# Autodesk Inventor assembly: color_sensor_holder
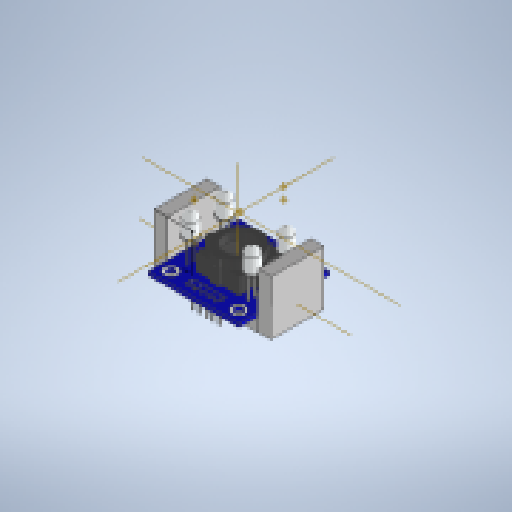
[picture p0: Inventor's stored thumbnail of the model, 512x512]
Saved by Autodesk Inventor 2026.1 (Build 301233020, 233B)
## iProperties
Created: 2026-10
Part Number: color_sensor_holder
Document SubType Name: Assembly
Designer: alolo
Author: alolo
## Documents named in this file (4)
- C:\Users\hp\Documents\Inventor\DOM1_CartesianRobot\color_sensor_holder.iam
- C:\Users\hp\Documents\Inventor\DOM1_CartesianRobot\color_sensor_holder_base.ipt
- C:\Users\hp\Documents\Inventor\DOM1_CartesianRobot\TCS3200 Color Sensor Module.ipt
- C:\Users\hp\Documents\Inventor\DOM1_CartesianRobot\color_sensor_holer_side.ipt
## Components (4 placed, 3 different names)
1. color_sensor_holder_base:1
2. TCS3200 Color Sensor Module:1 — Mate:1, Mate:13, Mate:33, Mate:34, Mate:35, Mate:36
3. color_sensor_holer_side:1 — Mate:31, Mate:39
4. color_sensor_holer_side:2 — Mate:15, Mate:40
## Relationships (10: Mate 10)
- Mate:1: TCS3200 Color Sensor Module:1
- Mate:13: TCS3200 Color Sensor Module:1
- Mate:15: color_sensor_holer_side:2
- Mate:31: color_sensor_holer_side:1
- Mate:33: TCS3200 Color Sensor Module:1
- Mate:34: TCS3200 Color Sensor Module:1
- Mate:35: TCS3200 Color Sensor Module:1
- Mate:36: TCS3200 Color Sensor Module:1
- Mate:39: color_sensor_holer_side:1
- Mate:40: color_sensor_holer_side:2
